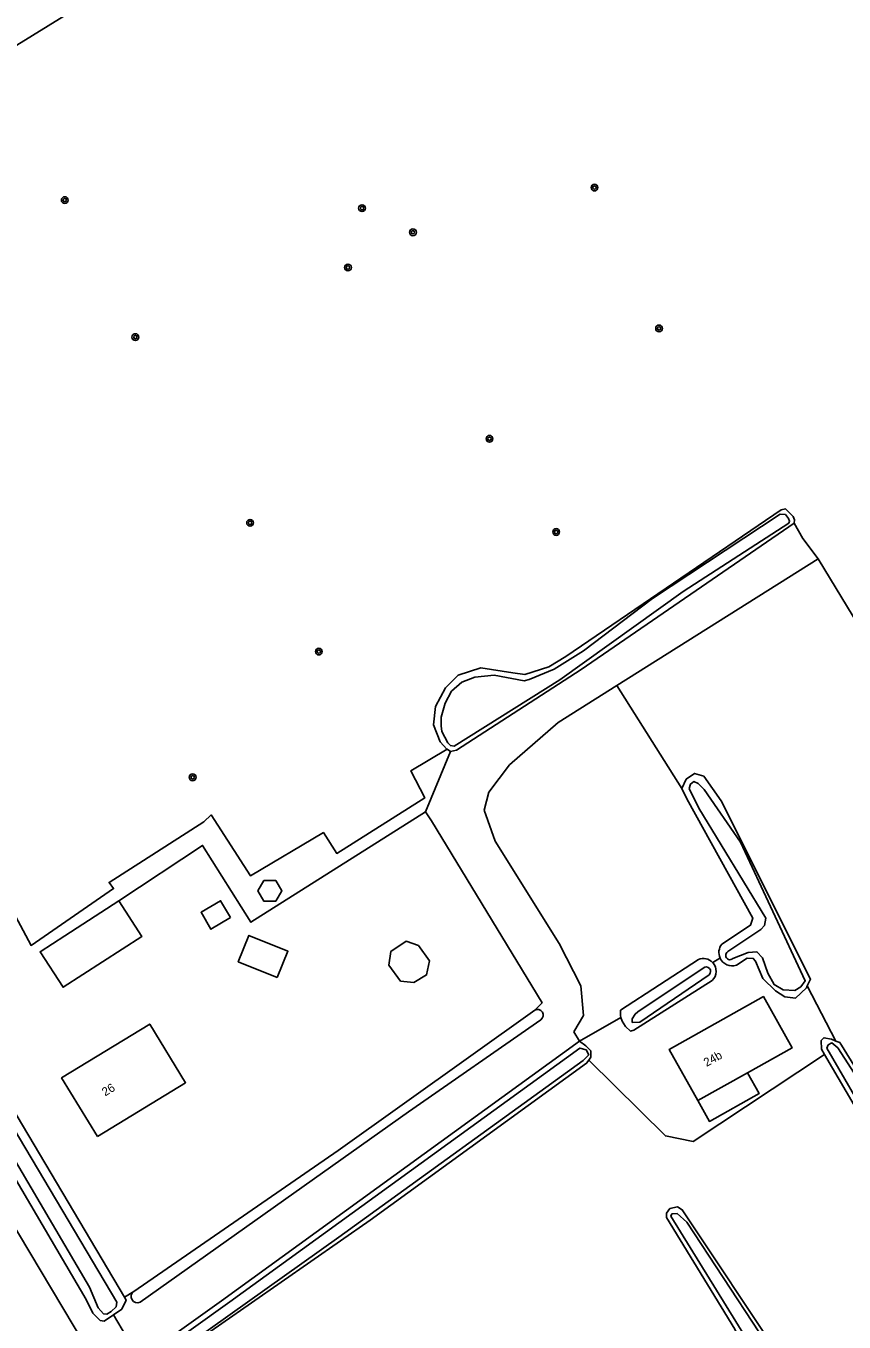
# Model space of a CAD drawing. Extents: x 137000 to 140001, y 403500 to 406000.
# Drawn here: x 139373.5 to 139469.8, y 404210.4 to 404363 of the extents above; entities that cross this region are included whole.
import ezdxf

# ---------------------------------------------------------------- set-up
doc = ezdxf.new("R2010")
doc.units = 0
for name, color, linetype in [('gg-afsc-erfafscheiding', 7, 'Continuous'), ('gg-afsc-hekwerk', 7, 'Continuous'), ('gg-anno-huisnummerreeks BGT', 7, 'Continuous'), ('gg-bbg-bijgebouw', 7, 'Continuous'), ('gg-bbg-hoofdgebouw', 7, 'Continuous'), ('gg-bbg-luifel en loopbrug', 7, 'Continuous'), ('gg-bbg-overig bouwwerk', 7, 'Continuous'), ('gg-knt-bronhoudergrens', 7, 'Continuous'), ('gg-knt-onverhard', 7, 'Continuous'), ('gg-knt-verharding', 7, 'Continuous'), ('gg-kntw-bovenkant insteek waterloop', 7, 'Continuous'), ('gg-kntw-waterlijn', 7, 'Continuous'), ('gt-grn-groengrens', 7, 'Continuous'), ('gt-grn-groengrens NZ', 7, 'Continuous'), ('gt-symb-boom', 7, 'Continuous')]:
    doc.layers.add(name, color=color, linetype=linetype)

# ---------------------------------------------------------------- blocks, each defined once
blk = doc.blocks.new('gt0-BOOM')
at = {"layer": 'gt-symb-boom'}
for radius in [0.4, 0.2]:
    blk.add_circle((0, 0), radius, dxfattribs=at)

msp = doc.modelspace()

# ---------------------------------------------------------------- linework, layer by layer
at = {"layer": 'gg-afsc-erfafscheiding'}
for p, q in [((139420.5, 404270.48), (139423.44, 404277.58)), ((139421.19, 404269.4), (139420.5, 404270.48)), ((139465.43, 404249.98), (139468.79, 404243.48)), ((139386.15, 404214), (139385.05, 404213.32))]:
    msp.add_line(p, q, dxfattribs=at)
for points in [[(139433.36, 404247.12), (139434.21, 404247.99), (139421.19, 404269.4)], [(139439.7, 404241.23), (139448.73, 404232.31), (139452, 404231.65), (139467.47, 404241.9)]]:
    msp.add_lwpolyline(points, dxfattribs=at)
at = {"layer": 'gg-afsc-hekwerk'}
msp.add_line((139420.5, 404270.48), (139421.19, 404269.4), dxfattribs=at)
msp.add_lwpolyline([(139384.4, 404260), (139394.25, 404266.52), (139399.93, 404257.46), (139420.5, 404270.48)], dxfattribs=at)
at = {"layer": 'gg-bbg-bijgebouw'}
msp.add_lwpolyline([(139384.4, 404260), (139378.03, 404255.87), (139375.13, 404254), (139377.84, 404249.81), (139387.11, 404255.81), (139384.4, 404260)], dxfattribs=at)
at = {"layer": 'gg-bbg-hoofdgebouw'}
msp.add_line((139458.38, 404239.74), (139452.54, 404236.47), dxfattribs=at)
for points in [[(139458.38, 404239.74), (139463.64, 404242.68), (139460.27, 404248.71), (139449.17, 404242.5), (139452.54, 404236.47)], [(139381.88, 404232.24), (139392.25, 404238.57), (139388.03, 404245.48), (139377.66, 404239.15), (139381.88, 404232.24)]]:
    msp.add_lwpolyline(points, dxfattribs=at)
at = {"layer": 'gg-bbg-luifel en loopbrug'}
for points in [[(139401.46, 404262.39), (139400.76, 404261.17), (139401.46, 404259.95), (139402.87, 404259.95), (139403.58, 404261.17), (139402.87, 404262.39), (139401.46, 404262.39)], [(139452.54, 404236.47), (139453.9, 404234.03), (139459.75, 404237.3), (139458.38, 404239.74)]]:
    msp.add_lwpolyline(points, dxfattribs=at)
at = {"layer": 'gg-bbg-overig bouwwerk'}
for points in [[(139397.54, 404258.01), (139396.36, 404259.99), (139394.07, 404258.64), (139395.24, 404256.65), (139397.54, 404258.01)], [(139403.03, 404250.96), (139404.29, 404254.05), (139399.7, 404255.92), (139398.45, 404252.82), (139403.03, 404250.96)], [(139419.67, 404254.75), (139418.21, 404255.23), (139416.42, 404254.04), (139416.17, 404252.43), (139417.55, 404250.55), (139419.13, 404250.37), (139420.61, 404251.27), (139420.96, 404252.92), (139419.67, 404254.75)]]:
    msp.add_lwpolyline(points, dxfattribs=at)
at = {"layer": 'gg-knt-bronhoudergrens'}
for p, q in [((139464.89, 404302.64), (139463.89, 404304.45)), ((139466.69, 404300.23), (139464.89, 404302.64)), ((139454.29, 404252.74), (139455.15, 404253.26)), ((139437.96, 404244.55), (139438.63, 404243.47))]:
    msp.add_line(p, q, dxfattribs=at)
for points in [[(139437.96, 404244.55), (139439.1, 404246.48), (139438.76, 404249.99), (139436.23, 404254.96), (139428.67, 404267.01), (139427.41, 404270.65), (139427.94, 404272.77), (139430.39, 404276.01), (139436.09, 404280.98), (139443.02, 404285.34)], [(139423.02, 404277.85), (139418.75, 404275.29), (139420.4, 404272.11), (139410.05, 404265.57), (139408.48, 404268.02), (139399.88, 404262.94), (139395.26, 404270.1), (139394.4, 404269.29), (139383.24, 404262.15), (139383.77, 404261.44), (139374.07, 404254.74), (139371.27, 404259.95)]]:
    msp.add_lwpolyline(points, dxfattribs=at)
at = {"layer": 'gg-knt-onverhard'}
msp.add_line((139443.49, 404246.27), (139438.63, 404243.47), dxfattribs=at)
at = {"layer": 'gg-knt-verharding'}
msp.add_line((139380.34, 404207.8), (139365.18, 404233.19), dxfattribs=at)
at = {"layer": 'gg-kntw-bovenkant insteek waterloop'}
for p, q in [((139423.44, 404277.58), (139423.02, 404277.85)), ((139385.05, 404213.32), (139370.42, 404238.01))]:
    msp.add_line(p, q, dxfattribs=at)
for points in [[(139316.86, 404325.67), (139343.48, 404342.59), (139370.54, 404359.57), (139398.22, 404376.67), (139422.44, 404392.03), (139454.18, 404412.04), (139484.08, 404430.64), (139513.57, 404449.21), (139533.95, 404462.1), (139549.03, 404471.7)], [(139422.23, 404278.72), (139421.44, 404280.71), (139421.65, 404282.86), (139422.85, 404285.07), (139424.35, 404286.54), (139426.99, 404287.41), (139430.76, 404286.81), (139432.19, 404286.64), (139434.99, 404287.54), (139437, 404288.75), (139462.34, 404306.01), (139462.87, 404306.13), (139463.77, 404305.25), (139463.91, 404304.83), (139463.89, 404304.45)], [(139423.44, 404277.58), (139424.15, 404277.72), (139438.83, 404287.21), (139463.89, 404304.45)], [(139423.02, 404277.85), (139423, 404277.86), (139422.23, 404278.72)], [(139465.43, 404249.98), (139465.81, 404250.76), (139455.29, 404271.77), (139453.24, 404274.67), (139452.16, 404274.99), (139451.17, 404274.31), (139450.64, 404273.21)], [(139450.64, 404273.21), (139451.23, 404272.01), (139459.01, 404257.94), (139458.76, 404257.11), (139455.37, 404254.9)], [(139452.61, 404253.09), (139443.43, 404247.1), (139443.43, 404246.5), (139443.49, 404246.27)], [(139465.43, 404249.98), (139465.32, 404249.75), (139464.02, 404248.55), (139462.77, 404248.68), (139461.67, 404249.39), (139460.2, 404250.84), (139459.33, 404252.89), (139459.06, 404253.22), (139458.35, 404253.23), (139457.08, 404252.42)], [(139443.49, 404246.27), (139443.62, 404245.81), (139444.04, 404245.21), (139444.62, 404244.66), (139445.02, 404244.75), (139454.23, 404250.61)], [(139433.36, 404247.12), (139410.21, 404230.61), (139386.15, 404214)], [(139386.9, 404212.75), (139418.5, 404235.14), (139434.05, 404246)], [(139387.68, 404206.64), (139396.48, 404212.89), (139438.63, 404243.47)], [(139439.7, 404241.23), (139439.96, 404241.57), (139439.93, 404242.33), (139439.35, 404242.93), (139438.63, 404243.47)], [(139467.47, 404241.9), (139467.1, 404242.53), (139467.06, 404243.54), (139467.39, 404243.87), (139468.26, 404243.71), (139468.79, 404243.48)], [(139467.47, 404241.9), (139495.21, 404194.46), (139510.84, 404170.09), (139511.54, 404169.24), (139512.74, 404169.28), (139513.56, 404170.14), (139513.81, 404171.21), (139469.24, 404243.3), (139468.79, 404243.48)], [(139389.11, 404204.68), (139389.55, 404205.37), (139413.96, 404222.41), (139439.45, 404240.88), (139439.7, 404241.23)], [(139383.76, 404211.26), (139382.66, 404210.5), (139382.2, 404210.57), (139381.32, 404211.47), (139380.55, 404213.07), (139367.09, 404235.95), (139367.36, 404236.41), (139370.42, 404238.01)], [(139462.35, 404206.12), (139486.61, 404166.69), (139495.97, 404152.33), (139495.87, 404151.34), (139494.75, 404150.61), (139493.4, 404150.24), (139492.84, 404150.82), (139492.2, 404151.72), (139458.75, 404205.22), (139456.9, 404209.55), (139448.86, 404222.72), (139448.84, 404223.23), (139449.26, 404223.76), (139450.13, 404223.96), (139450.7, 404223.62), (139462.35, 404206.12)], [(139385.05, 404213.32), (139385.24, 404213), (139384.73, 404211.92), (139383.76, 404211.26)]]:
    msp.add_lwpolyline(points, dxfattribs=at)
for centre, radius, start, end in [((139456.58, 404253.9), 1.56, 140.3373, 204.4779), ((139453.19, 404251.7), 1.51, 43.3396, 112.7181), ((139453.19, 404251.7), 1.51, 313.5602, 43.3144), ((139456.58, 404253.9), 1.56, 204.4193, 288.5726), ((139433.68, 404246.55), 0.661, 303.76, 119.239), ((139386.57, 404213.4), 0.728, 124.6608, 297.2938)]:
    msp.add_arc(centre, radius, start, end, dxfattribs=at)
at = {"layer": 'gg-kntw-waterlijn'}
for points in [[(139450.83, 404296.42), (139463.27, 404304.45), (139463.34, 404304.68), (139463.23, 404305), (139462.86, 404305.48), (139462.25, 404305.51), (139447.22, 404295.58), (139439.09, 404289.42), (139435.62, 404287.26), (139432.69, 404286.03), (139432.12, 404285.88), (139428.59, 404286.54), (139426.28, 404286.3), (139424.77, 404285.75), (139423.55, 404284.66), (139422.82, 404283.27), (139422.32, 404281.61), (139422.32, 404280.6), (139422.43, 404279.93), (139423.1, 404278.6), (139423.43, 404278.26), (139423.85, 404278.19), (139436.3, 404286), (139450.83, 404296.42)], [(139456.67, 404253.19), (139458.47, 404253.89), (139459.49, 404253.99), (139460.17, 404253.29), (139460.8, 404251.49), (139461.53, 404250.14), (139462.6, 404249.52), (139463.97, 404249.44), (139464.67, 404249.88), (139465.18, 404250.56), (139457.55, 404266.9), (139453.3, 404273.09), (139452.57, 404273.79), (139452.09, 404274.03), (139451.67, 404273.74), (139451.54, 404273.2), (139452.65, 404270.91), (139460.53, 404257.95), (139460.37, 404257.09), (139459.95, 404256.61), (139456.07, 404254.01)], [(139453.17, 404252.07), (139445.49, 404246.92), (139445.16, 404246.66), (139444.83, 404246.1), (139444.82, 404245.68), (139445.72, 404245.72), (139453.88, 404251.29)], [(139512.38, 404169.98), (139512.85, 404170.64), (139513, 404171.56), (139489.71, 404208.76), (139476.37, 404231.31), (139469.02, 404242.68), (139468.31, 404243.27), (139467.87, 404243.02), (139467.74, 404242.66), (139494.61, 404196.35), (139511.3, 404170.23), (139511.99, 404169.92), (139512.38, 404169.98)], [(139388.09, 404206.08), (139397.44, 404212.79), (139438.66, 404242.65), (139439.38, 404242.44), (139439.7, 404241.85), (139439.03, 404241.2), (139410.28, 404220.39), (139388.79, 404205.11)], [(139368.3, 404236.48), (139369.45, 404237.2), (139369.78, 404236.87), (139384.15, 404212.75), (139384.06, 404212.21), (139383.49, 404211.66), (139382.98, 404211.32), (139382.57, 404211.38), (139381.98, 404212.08), (139380.93, 404214.5), (139368.23, 404236.08), (139368.3, 404236.48)], [(139493.13, 404151.52), (139493.71, 404151.05), (139494.61, 404151.33), (139495.11, 404151.82), (139495.35, 404152.44), (139479.68, 404176.18), (139459.8, 404209.14), (139451.24, 404222.16), (139450.1, 404223.2), (139449.5, 404223.14), (139449.37, 404222.88), (139458.17, 404208.61), (139459.8, 404204.86), (139481.58, 404170.15), (139493.13, 404151.52)]]:
    msp.add_lwpolyline(points, dxfattribs=at)
for centre, radius, start, end in [((139456.33, 404253.57), 0.511, 121.0769, 311.6728), ((139453.52, 404251.68), 0.528, 312.8175, 131.5766)]:
    msp.add_arc(centre, radius, start, end, dxfattribs=at)
at = {"layer": 'gt-grn-groengrens'}
for p, q in [((139443.02, 404285.34), (139450.64, 404273.21)), ((139383.76, 404211.26), (139386.87, 404206.06))]:
    msp.add_line(p, q, dxfattribs=at)
msp.add_lwpolyline([(139466.69, 404300.23), (139474.94, 404286.67), (139542.73, 404178.2)], dxfattribs=at)
at = {"layer": 'gt-grn-groengrens NZ'}
msp.add_line((139443.02, 404285.34), (139466.69, 404300.23), dxfattribs=at)

# ---------------------------------------------------------------- block references
at = {"layer": 'gt-symb-boom'}
for p in [(139440.38, 404343.95), (139378.03, 404342.48), (139413.02, 404341.53), (139419.01, 404338.69), (139411.36, 404334.54), (139386.34, 404326.35), (139447.98, 404327.37), (139428.02, 404314.38), (139399.84, 404304.49), (139435.87, 404303.41), (139407.93, 404289.33), (139393.08, 404274.53)]:
    msp.add_blockref('gt0-BOOM', p, dxfattribs=at)

# ---------------------------------------------------------------- texts
at = {"layer": 'gg-anno-huisnummerreeks BGT'}
for s, rotation, p in [('24b', 29.2, (139453.57, 404240.43)), ('26', 31.4, (139382.78, 404236.95))]:
    msp.add_text(s, height=1, rotation=rotation, dxfattribs=at).set_placement(p)

doc.saveas('drawing.dxf')
